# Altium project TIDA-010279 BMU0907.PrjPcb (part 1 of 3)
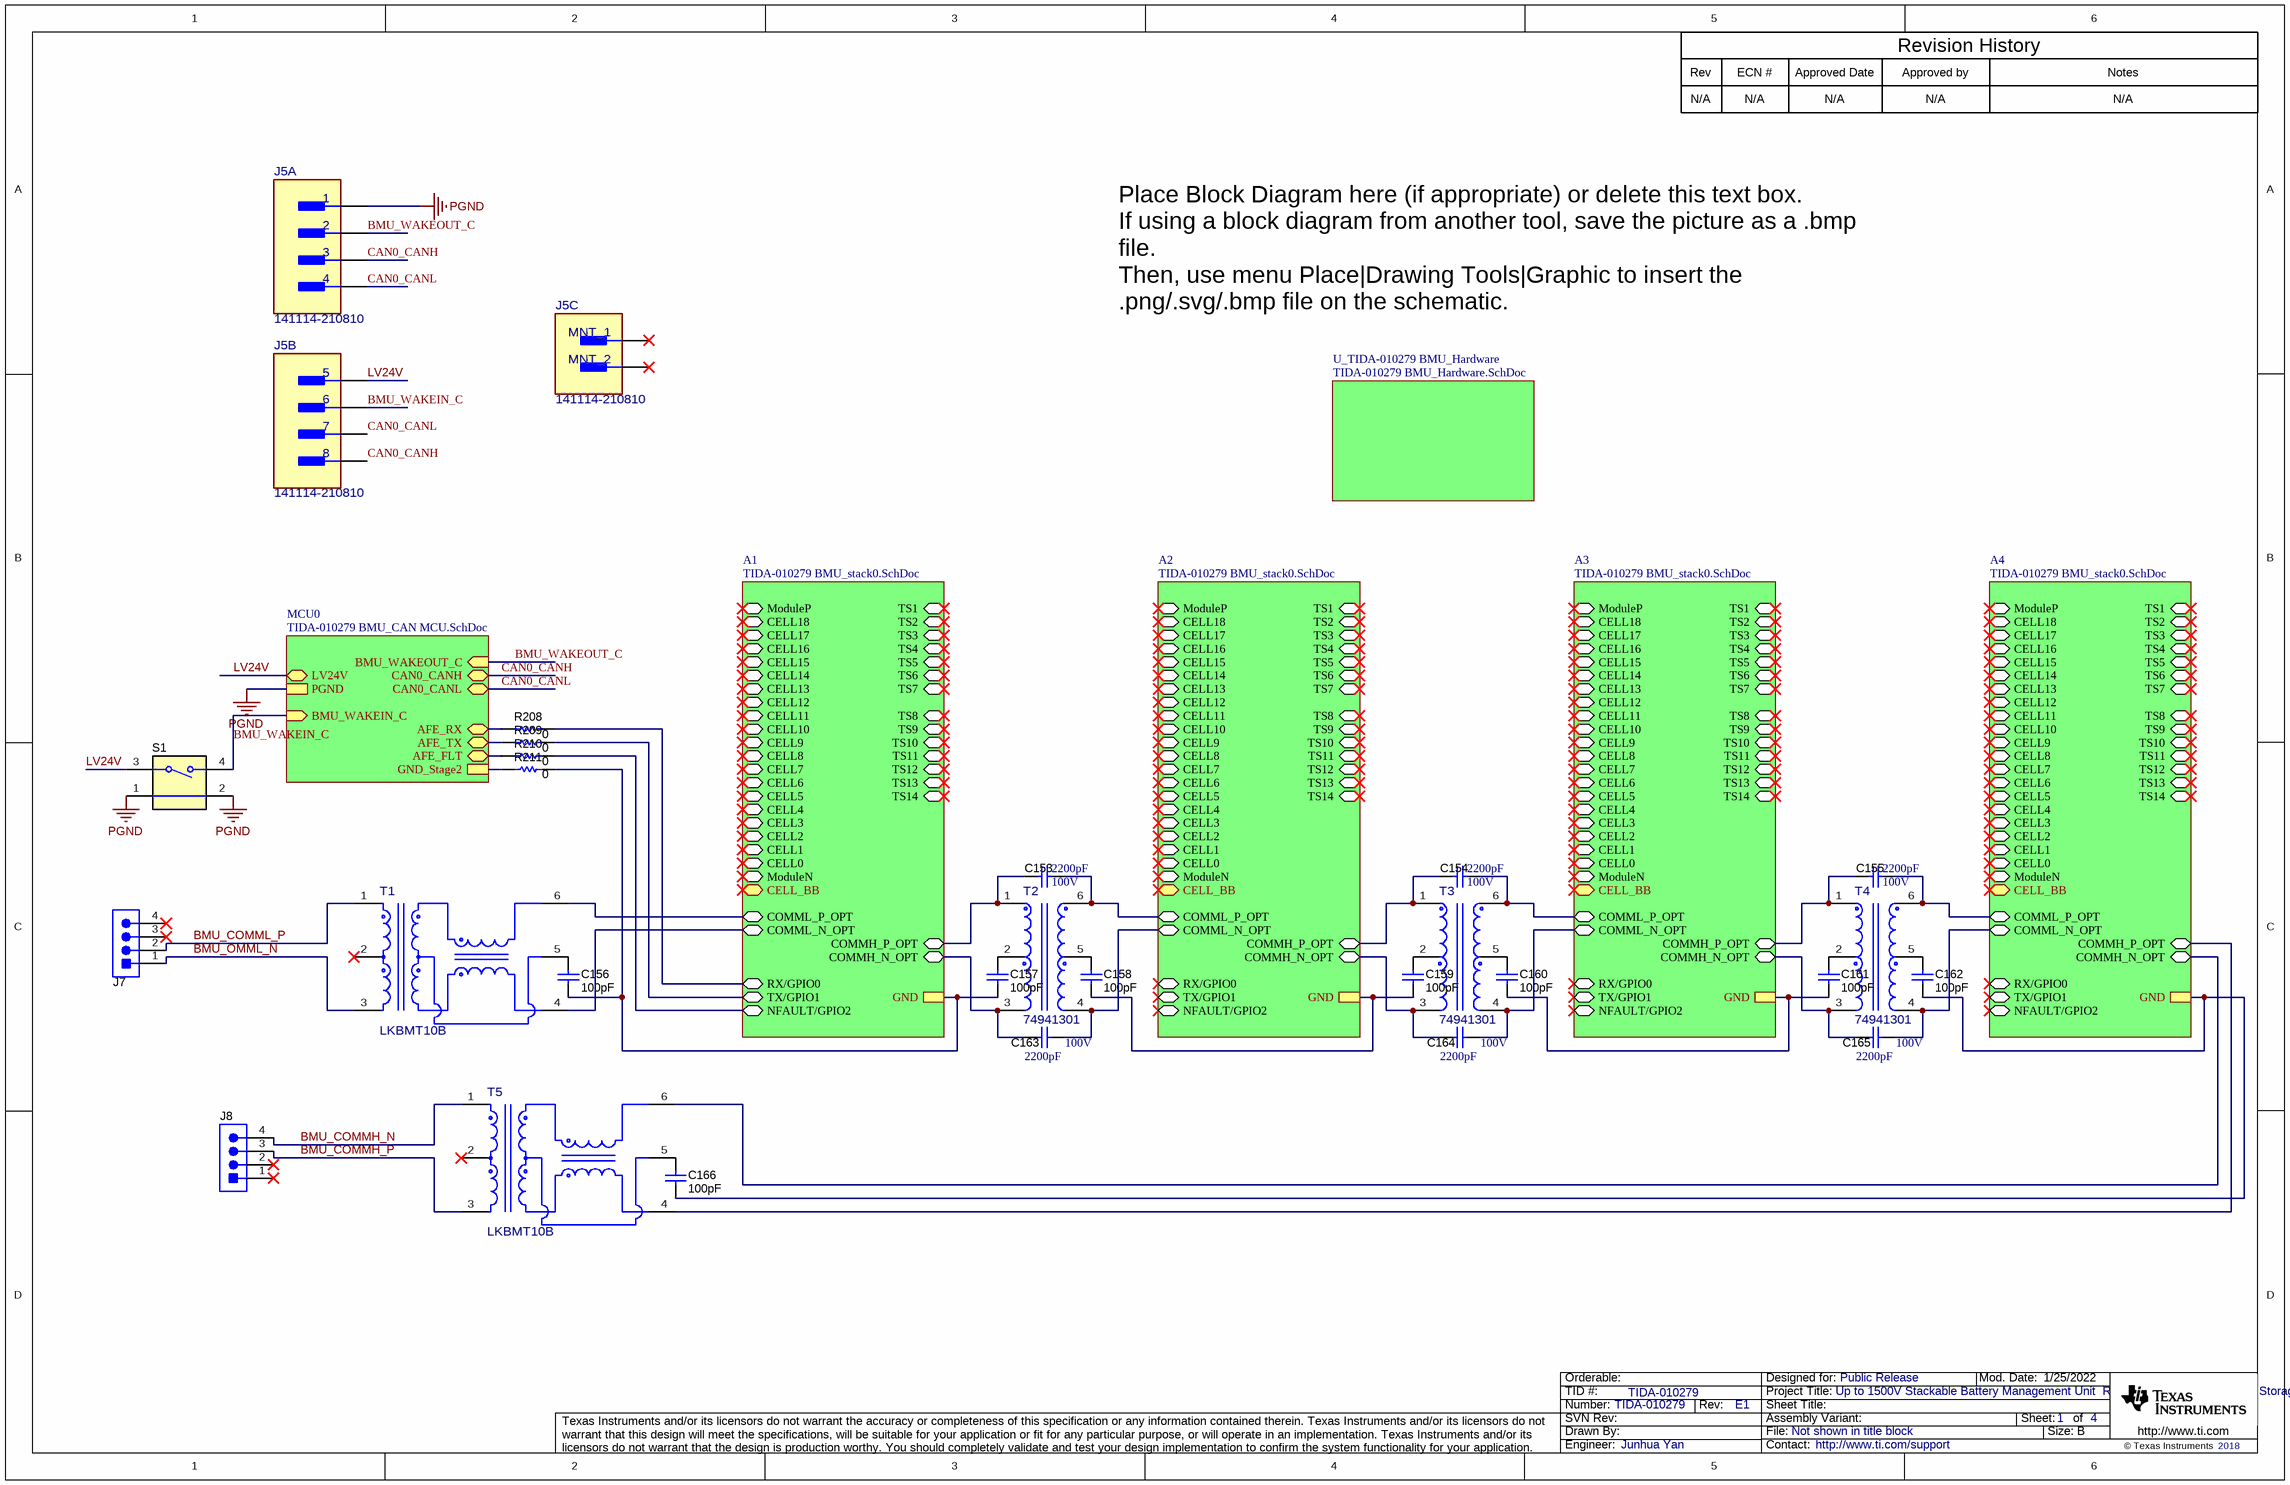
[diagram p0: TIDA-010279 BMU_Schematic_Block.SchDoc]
TID: TIDA-010279; TechSupport: http://www.ti.com/support; SCH_Rev: E1; PRJ_Title: Up to 1500V Stackable Battery Management Unit  Reference Design for Energy Storage Systems; PRJ_Number: TIDA-010279; PRJ_Engineer: Junhua Yan; PRJ_Customer: Public Release; PCB_Rev: E1; PCB_Layout: Junhua Yan; Orderable: N/A; CopyrightYear: 2018
4 sheets, 1439 parts. Net scope: hierarchical (ports join the sheet entries above them; power ports are global).
Board file: TIDA-010279 BMU0829.PcbDoc
Sheets:
  TIDA-010279 BMU_Schematic_Block.SchDoc
    A1 = TIDA-010279 BMU_stack0.SchDoc
    MCU0 = TIDA-010279 BMU_CAN MCU.SchDoc
    A2 = TIDA-010279 BMU_stack0.SchDoc
    A3 = TIDA-010279 BMU_stack0.SchDoc
    A4 = TIDA-010279 BMU_stack0.SchDoc
    U_TIDA-010279 BMU_Hardware = TIDA-010279 BMU_Hardware.SchDoc

## Sheet TIDA-010279 BMU_Schematic_Block.SchDoc
size 431 x 279 mm; Date: Not shown in title block; ApprovedBy: Not shown in title block; CheckedBy: Not shown in title block; Author: Not shown in title block; CompanyName: Not shown in title block; Engineer: Not shown in title block; Organization: Not shown in title block; Address1: Not shown in title block; Address2: Not shown in title block; Address3: Not shown in title block; Address4: Not shown in title block; DocumentNumber: 1; Revision: Use project parameter SCH_Rev; SheetNumber: 1; SheetTotal: 4; PageSetup: Record=PageOptions¦CenterHorizontal=True¦CenterVertical=True¦PrintScale=1.00¦XCorrection=1.00¦YCorrection=1.00¦PrintKind=0¦BorderSize=5000000¦LeftOffset=0¦BottomOffset=0¦Orientation=2¦PaperLength=1000¦PaperWidth=1000¦Scale=100¦PaperSource=15¦PrintQuality=600¦MediaType=1¦DitherType=10¦PaperKind=Letter¦PrintScaleMode=1

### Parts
C153  VDC_V: 100V  ValueDisplayed: 2200pF  [1206]  (hidden comment: 12061A222JAT2A)
C154  VDC_V: 100V  ValueDisplayed: 2200pF  [1206]  (hidden comment: 12061A222JAT2A)
C155  VDC_V: 100V  ValueDisplayed: 2200pF  [1206]  (hidden comment: 12061A222JAT2A)
C156  ValueDisplayed: 100pF  [0603]  (hidden comment: GCM1885C1H101JA16J)
C157  ValueDisplayed: 100pF  [0603]  (hidden comment: GCM1885C1H101JA16J)
C158  ValueDisplayed: 100pF  [0603]  (hidden comment: GCM1885C1H101JA16J)
C159  ValueDisplayed: 100pF  [0603]  (hidden comment: GCM1885C1H101JA16J)
C160  ValueDisplayed: 100pF  [0603]  (hidden comment: GCM1885C1H101JA16J)
C161  ValueDisplayed: 100pF  [0603]  (hidden comment: GCM1885C1H101JA16J)
C162  ValueDisplayed: 100pF  [0603]  (hidden comment: GCM1885C1H101JA16J)
C163  VDC_V: 100V  ValueDisplayed: 2200pF  [1206]  (hidden comment: 12061A222JAT2A)
C164  VDC_V: 100V  ValueDisplayed: 2200pF  [1206]  (hidden comment: 12061A222JAT2A)
C165  VDC_V: 100V  ValueDisplayed: 2200pF  [1206]  (hidden comment: 12061A222JAT2A)
C166  ValueDisplayed: 100pF  [0603]  (hidden comment: GCM1885C1H101JA16J)
J5  141114-210810  [FP-141114-210810_CONN_HDR16-MFG]  (parts A,B,C of 3)
J7  70551-0038  [Molex_70551-0038]  (value not drawn)
J8  70551-0038  [Molex_70551-0038]  (value not drawn)
R208  ValueDisplayed: 0  [0402]  (hidden comment: CRCW04020000Z0ED)
R209  ValueDisplayed: 0  [0402]  (hidden comment: CRCW04020000Z0ED)
R210  ValueDisplayed: 0  [0402]  (hidden comment: CRCW04020000Z0ED)
R211  ValueDisplayed: 0  [0402]  (hidden comment: CRCW04020000Z0ED)
S1  1188E-1K2-V-TR  [SW_1188E]  (value not drawn)
T1  LKBMT10B  [FP-LKBMT10B_SMT_XFRMR_27MM9_12MM5-MFG]
T2  74941301  [FP-HMU1228NL_SMT_TRANSFORMER_8MM89_10MM09-MFG]
T3  74941301  [FP-HMU1228NL_SMT_TRANSFORMER_8MM89_10MM09-MFG]
T4  74941301  [FP-HMU1228NL_SMT_TRANSFORMER_8MM89_10MM09-MFG]
T5  LKBMT10B  [FP-LKBMT10B_SMT_XFRMR_27MM9_12MM5-MFG]

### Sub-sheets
A1 = TIDA-010279 BMU_stack0.SchDoc: ModuleP (bidir), CELL9 (bidir), CELL10 (bidir), CELL11 (bidir), CELL12 (bidir), CELL13 (bidir), CELL14 (bidir), CELL15 (bidir), CELL16 (bidir), CELL8 (bidir), CELL17 (bidir), CELL18 (bidir), ModuleN (bidir), CELL1 (bidir), CELL2 (bidir), CELL3 (bidir), CELL4 (bidir), CELL5 (bidir), CELL6 (bidir), CELL7 (bidir), CELL0 (bidir), TS1 (bidir), TS2 (bidir), TS3 (bidir), TS4 (bidir), TS5 (bidir), TS6 (bidir), TS7 (bidir), TS8 (bidir), TS9 (bidir), TS10 (bidir), TS11 (bidir), TS12 (bidir), TS13 (bidir), TS14 (bidir), COMML_N_OPT (bidir), COMML_P_OPT (bidir), COMMH_N_OPT (bidir), COMMH_P_OPT (bidir), CELL_BB (bidir), GND, NFAULT/GPIO2 (bidir), TX/GPIO1 (bidir), RX/GPIO0 (bidir)
A2 = TIDA-010279 BMU_stack0.SchDoc: ModuleP (bidir), CELL9 (bidir), CELL10 (bidir), CELL11 (bidir), CELL12 (bidir), CELL13 (bidir), CELL14 (bidir), CELL15 (bidir), CELL16 (bidir), CELL8 (bidir), CELL17 (bidir), CELL18 (bidir), ModuleN (bidir), CELL1 (bidir), CELL2 (bidir), CELL3 (bidir), CELL4 (bidir), CELL5 (bidir), CELL6 (bidir), CELL7 (bidir), CELL0 (bidir), TS1 (bidir), TS2 (bidir), TS3 (bidir), TS4 (bidir), TS5 (bidir), TS6 (bidir), TS7 (bidir), TS8 (bidir), TS9 (bidir), TS10 (bidir), TS11 (bidir), TS12 (bidir), TS13 (bidir), TS14 (bidir), COMML_N_OPT (bidir), COMML_P_OPT (bidir), COMMH_N_OPT (bidir), COMMH_P_OPT (bidir), CELL_BB (bidir), GND, NFAULT/GPIO2 (bidir), TX/GPIO1 (bidir), RX/GPIO0 (bidir)
A3 = TIDA-010279 BMU_stack0.SchDoc: ModuleP (bidir), CELL9 (bidir), CELL10 (bidir), CELL11 (bidir), CELL12 (bidir), CELL13 (bidir), CELL14 (bidir), CELL15 (bidir), CELL16 (bidir), CELL8 (bidir), CELL17 (bidir), CELL18 (bidir), ModuleN (bidir), CELL1 (bidir), CELL2 (bidir), CELL3 (bidir), CELL4 (bidir), CELL5 (bidir), CELL6 (bidir), CELL7 (bidir), CELL0 (bidir), TS1 (bidir), TS2 (bidir), TS3 (bidir), TS4 (bidir), TS5 (bidir), TS6 (bidir), TS7 (bidir), TS8 (bidir), TS9 (bidir), TS10 (bidir), TS11 (bidir), TS12 (bidir), TS13 (bidir), TS14 (bidir), COMML_N_OPT (bidir), COMML_P_OPT (bidir), COMMH_N_OPT (bidir), COMMH_P_OPT (bidir), CELL_BB (bidir), GND, NFAULT/GPIO2 (bidir), TX/GPIO1 (bidir), RX/GPIO0 (bidir)
A4 = TIDA-010279 BMU_stack0.SchDoc: ModuleP (bidir), CELL9 (bidir), CELL10 (bidir), CELL11 (bidir), CELL12 (bidir), CELL13 (bidir), CELL14 (bidir), CELL15 (bidir), CELL16 (bidir), CELL8 (bidir), CELL17 (bidir), CELL18 (bidir), ModuleN (bidir), CELL1 (bidir), CELL2 (bidir), CELL3 (bidir), CELL4 (bidir), CELL5 (bidir), CELL6 (bidir), CELL7 (bidir), CELL0 (bidir), TS1 (bidir), TS2 (bidir), TS3 (bidir), TS4 (bidir), TS5 (bidir), TS6 (bidir), TS7 (bidir), TS8 (bidir), TS9 (bidir), TS10 (bidir), TS11 (bidir), TS12 (bidir), TS13 (bidir), TS14 (bidir), COMML_N_OPT (bidir), COMML_P_OPT (bidir), COMMH_N_OPT (bidir), COMMH_P_OPT (bidir), CELL_BB (bidir), GND, NFAULT/GPIO2 (bidir), TX/GPIO1 (bidir), RX/GPIO0 (bidir)
MCU0 = TIDA-010279 BMU_CAN MCU.SchDoc: CAN0_CANH (bidir), CAN0_CANL (bidir), BMU_WAKEOUT_C (in), BMU_WAKEIN_C (in), LV24V (bidir), GND_Stage2, PGND, AFE_FLT (bidir), AFE_TX (bidir), AFE_RX (bidir)
U_TIDA-010279 BMU_Hardware = TIDA-010279 BMU_Hardware.SchDoc: no entries

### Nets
GND: C156.1 C157.1 C158.1 C159.1 C160.1 C161.1 C162.1 C166.1 R211.1 ; sheet A1/GND, sheet A2/GND, sheet A3/GND, sheet A4/GND
GND_Stage2: R211.2 ; sheet MCU0/GND_Stage2
PGND: J5.1 S1.1 S1.2 ; sheet MCU0/PGND
AFE_FLT: R210.2 ; sheet MCU0/AFE_FLT
AFE_RX: R208.2 ; sheet MCU0/AFE_RX
AFE_TX: R209.2 ; sheet MCU0/AFE_TX
BMU_COMMH_N: J8.4 T5.1
BMU_COMMH_P: J8.3 T5.3
BMU_COMML_P: J7.2 T1.1
BMU_OMML_N: J7.1 T1.3
BMU_WAKEIN_C: J5.6 S1.4 ; sheet MCU0/BMU_WAKEIN_C
BMU_WAKEOUT_C: J5.2 ; sheet MCU0/BMU_WAKEOUT_C
CAN0_CANH: J5.3 J5.8 ; sheet MCU0/CAN0_CANH
CAN0_CANL: J5.4 J5.7 ; sheet MCU0/CAN0_CANL
COMMH_N_OPT: C163.1 T2.3(TD-) ; sheet A1/COMMH_N_OPT
COMMH_N_OPT: C164.1 T3.3(TD-) ; sheet A2/COMMH_N_OPT  [a separate net that carries the same name]
COMMH_N_OPT: C165.1 T4.3(TD-) ; sheet A3/COMMH_N_OPT  [a separate net that carries the same name]
COMMH_N_OPT: T5.6 ; sheet A4/COMMH_N_OPT  [a separate net that carries the same name]
COMMH_P_OPT: C153.2 T2.1(TD+) ; sheet A1/COMMH_P_OPT
COMMH_P_OPT: C154.2 T3.1(TD+) ; sheet A2/COMMH_P_OPT  [a separate net that carries the same name]
COMMH_P_OPT: C155.2 T4.1(TD+) ; sheet A3/COMMH_P_OPT  [a separate net that carries the same name]
COMMH_P_OPT: T5.4 ; sheet A4/COMMH_P_OPT  [a separate net that carries the same name]
COMML_N_OPT: C163.2 T2.4(TX-) ; sheet A2/COMML_N_OPT
COMML_N_OPT: C164.2 T3.4(TX-) ; sheet A3/COMML_N_OPT  [a separate net that carries the same name]
COMML_N_OPT: C165.2 T4.4(TX-) ; sheet A4/COMML_N_OPT  [a separate net that carries the same name]
COMML_N_OPT: T1.4 ; sheet A1/COMML_N_OPT  [a separate net that carries the same name]
COMML_P_OPT: C153.1 T2.6(TX+) ; sheet A2/COMML_P_OPT
COMML_P_OPT: C154.1 T3.6(TX+) ; sheet A3/COMML_P_OPT  [a separate net that carries the same name]
COMML_P_OPT: C155.1 T4.6(TX+) ; sheet A4/COMML_P_OPT  [a separate net that carries the same name]
COMML_P_OPT: T1.6 ; sheet A1/COMML_P_OPT  [a separate net that carries the same name]
LV24V: J5.5 S1.3 ; sheet MCU0/LV24V
NFAULT/GPIO2: R210.1 ; sheet A1/NFAULT/GPIO2
RX/GPIO0: R208.1 ; sheet A1/RX/GPIO0
TX/GPIO1: R209.1 ; sheet A1/TX/GPIO1
NetC156_2: C156.2 T1.5
NetC157_2: C157.2 T2.2(TCT)
NetC158_2: C158.2 T2.5(CMT)
NetC159_2: C159.2 T3.2(TCT)
NetC160_2: C160.2 T3.5(CMT)
NetC161_2: C161.2 T4.2(TCT)
NetC162_2: C162.2 T4.5(CMT)
NetC166_2: C166.2 T5.5

Not connected (* = marked no-connect by the designer): J5 9(MNT_1)* 10(MNT_2)*; J7 3* 4*; J8 1* 2*; T1 2*; T5 2*

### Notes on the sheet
- Rev
- N/A
- ECN #
- Approved Date
- Approved by
- Revision History
- Notes
- Place Block Diagram here (if appropriate) or delete this text box.
  If using a block diagram from another tool, save the picture as a .bmp file.
  Then, use menu Place|Drawing Tools|Graphic to insert the .png/.svg/.bmp file on the schematic.

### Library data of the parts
C153-C155 C163-C165 = CMP-0008473-2: CAP, CERM, 2200 pF, 100 V, +/- 5%, C0G/NP0, 1206; Manufacturer: AVX; TaMin_C: -55°C; ESR_ohm: 1.73d; Polarized: N; SizeAreaWB_mm2: 10.92; Value1: 0.173 ohm; U/M: EA; Value: 2200pF; TaMax_C: 125°C; SizeZ_mm: 1.35; SizeX_mm: 3.2; SizeY_mm: 1.6; SizeArea_mm2: 5.12; Cap_F: 2.2nF; AEC Category: Q200
C156-C162 C166 = CMP-0750041-1: CAP, CERM, 100 pF, 50 V,+/- 5%, C0G/NP0, AEC-Q200 Grade 1, 0603; Manufacturer: MuRata; TaMin_C: -55°C; Polarized: N; SizeAreaWB_mm2: 4.68; U/M: EA; Value: 100pF; TaMax_C: 125°C; SizeZ_mm: 1; SizeX_mm: 1.6; SizeY_mm: 0.8; Value2: 50V; SizeArea_mm2: 1.28; AEC Qualified: Y; AEC Category: Q200
J5 = CMP-0091530-1: 2.00mm R/A SMT WAFER 8PIN KEY-A WITH CPA FEATURE; Manufacturer: BEIJIDA ELECTRONICS TECHNOLOGY; ContactFinish: Tin,Nickel; Current_A: 3A; Row_Count: 2; Voltage_V: 60V; AEC Grade: NA; AEC Qualified: No; Conn Gender: Male; Conn Orientation: Right Angle; DUT-Pitch_mm: 2mm; SizeZ_mm: 9.6mm
J7 J8 = CMP-0055239-1: Header(shrouded), 2.54mm, 4x1, R/A, Gold, TH; Manufacturer: Molex; CNHeader: FALSE; Current_A: 3A; Green_Lifecycle: Active; Shrouded: Y; Gender: Male; Green_REACh: Passed; Voltage_V: 250V; Row_Count: 1; Pitch_mm: 2.54
R208-R211 = CMP-0026822-3: RES, 0, 5%, 0.063 W, AEC-Q200 Grade 0, 0402; Manufacturer: Vishay-Dale; Power_W: 63mW; TempCo: 200 ppm/C; Value_Code: 0000; Value: 0; EIA_Code: E24; SizeX_mm: 1; SizeY_mm: 0.5; SizeZ_mm: 0.6; Value2: 0.063W; AEC Qualified: Y; VDC_V: 50V; AEC Category: Q200
S1 = CMP-0002328-1: Switch, SPST, 0.05 A, 12 VDC, SMD; Manufacturer: Diptronics; CurrentRating_mA: 50A; PositionCount: 1; SizeX_mm: 7.8; SizeY_mm: 3.5; SizeArea_mm2: 27.3; VDC_V: 12V; SizeAreaWB_mm2: 53.9
T1 T5 = CMP-0122349-1: SMD BMS Transformer; Manufacturer: LineKey Technology; DCR_ohm: 0.8; Ind_H: 300µH; Ns1toNp: 1:1; Rsec1_ohm: 1; SizeZ_mm: 9.5mm; AEC Qualified: Yes; AEC Grade: Grade 1; Insertion Loss: -0.5dB; Return Loss: -20dB; Voltage_Isolation_Vrms: 5000VDC
T2-T4 = CMP-0086619-1: BMS TRANSFORMER; Manufacturer: Wurth Elektronik; Ns1toNp: 1:1; Ind_H: 150µH; SizeZ_mm: 6.85mm; AEC Grade: Grade 1; AEC Qualified: Yes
